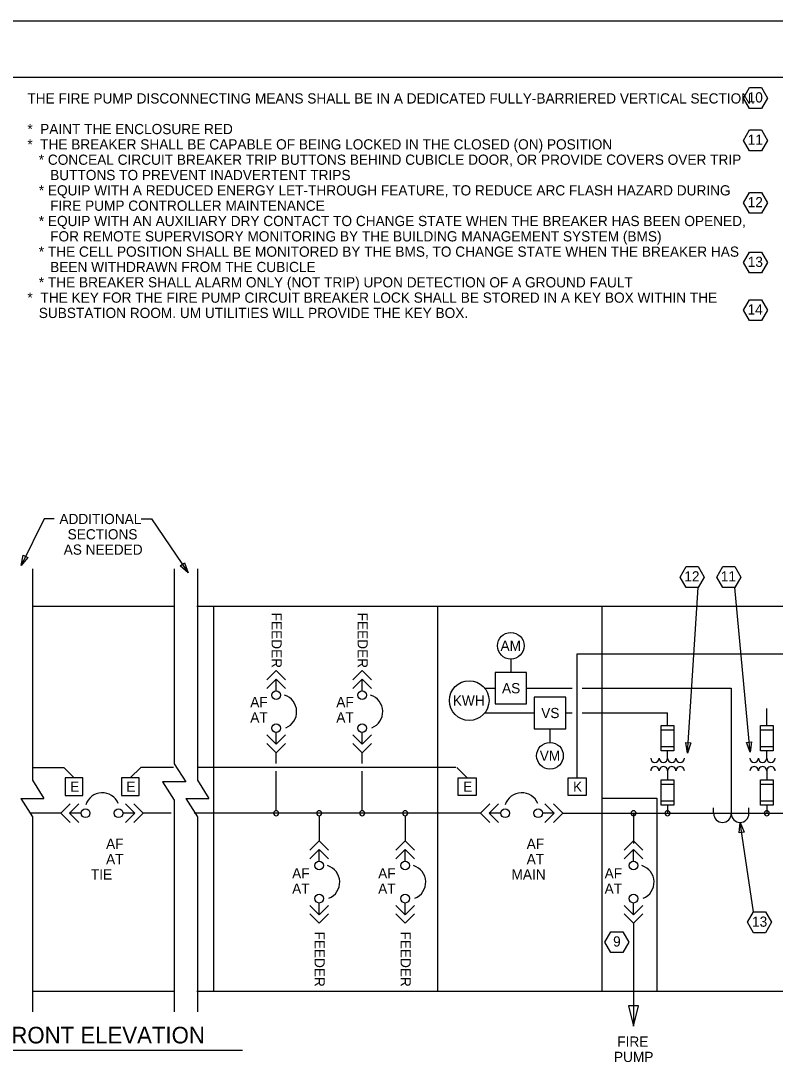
# Model space of a CAD drawing. Extents: x 10251 to 10396, y 10092 to 10197.
# Drawn here: x 10316 to 10365.3, y 10129 to 10196.9 of the extents above; entities that cross this region are included whole.
import ezdxf

# ---------------------------------------------------------------- set-up
doc = ezdxf.new("R2010")
doc.units = 0
for name, color, linetype in [('Default', 7, 'Continuous'), ('G-ANNO-TEXT', 7, 'Continuous'), ('G-ANNO-TTLB', 7, 'Continuous'), ('G-DETL-LINE', 7, 'Continuous'), ('G-DETL-OTLN', 7, 'Continuous'), ('G-DETL-PATT', 7, 'Continuous')]:
    doc.layers.add(name, color=color, linetype=linetype)

msp = doc.modelspace()

# ---------------------------------------------------------------- linework, layer by layer
at = {"layer": 'Default'}
for p, q in [((10323.872, 10164.429), (10324.538, 10164.429)), ((10357.833, 10150.946), (10358.656, 10150.946)), ((10357.833, 10149.298), (10357.833, 10150.946)), ((10357.833, 10150.672), (10358.656, 10150.672)), ((10358.656, 10150.946), (10358.656, 10149.298)), ((10332.687, 10148.464), (10332.687, 10149.17)), ((10338.305, 10148.464), (10338.305, 10149.17)), ((10357.833, 10149.573), (10358.656, 10149.573)), ((10358.656, 10149.298), (10357.833, 10149.298)), ((10338.305, 10145.388), (10338.305, 10147.964)), ((10316.017, 10146.186), (10316.771, 10144.994)), ((10335.496, 10145.063), (10335.496, 10143.418))]:
    msp.add_line(p, q, dxfattribs=at)
for points in [[(10364.774, 10191.899), (10364.382, 10191.219), (10363.598, 10191.219), (10363.206, 10191.899), (10363.598, 10192.578), (10364.382, 10192.578)], [(10355.717, 10136.816), (10355.325, 10136.137), (10354.541, 10136.137), (10354.149, 10136.816), (10354.541, 10137.495), (10355.325, 10137.495)]]:
    msp.add_lwpolyline(points, close=True, dxfattribs=at)
for centre, start, end in [((10332.687, 10145.226), 360, 180), ((10332.687, 10145.226), 180, 0), ((10335.496, 10145.226), 360, 180), ((10335.496, 10145.226), 180, 0), ((10341.114, 10145.226), 360, 180), ((10341.114, 10145.226), 180, 0), ((10364.723, 10145.225), 360, 180), ((10364.723, 10145.225), 180, 0)]:
    msp.add_arc(centre, 0.163, start, end, dxfattribs=at)
at = {"layer": 'G-ANNO-TEXT'}
for p, q in [((10290.736, 10193.271), (10393.489, 10193.271)), ((10317.535, 10164.429), (10316.027, 10161.402)), ((10318.201, 10164.429), (10317.535, 10164.429)), ((10324.538, 10164.429), (10326.937, 10160.917)), ((10316.771, 10161.18), (10316.771, 10147.379)), ((10326.027, 10161.18), (10326.027, 10148.458)), ((10327.542, 10161.18), (10327.542, 10147.379)), ((10359.557, 10149.156), (10360.244, 10159.962)), ((10363.628, 10149.203), (10362.629, 10159.962)), ((10326.027, 10148.458), (10326.781, 10147.266)), ((10316.771, 10147.379), (10317.526, 10146.186)), ((10326.781, 10147.266), (10325.272, 10147.266)), ((10325.272, 10147.266), (10326.027, 10146.073)), ((10327.542, 10147.379), (10328.297, 10146.186)), ((10316.017, 10146.186), (10317.526, 10146.186)), ((10326.027, 10146.073), (10326.027, 10132.272)), ((10326.787, 10146.186), (10328.297, 10146.186)), ((10326.787, 10146.186), (10327.542, 10144.994)), ((10316.771, 10144.994), (10316.771, 10132.272)), ((10327.542, 10144.994), (10327.542, 10132.272)), ((10363.858, 10138.787), (10362.981, 10144.63)), ((10312.797, 10129.772), (10330.484, 10129.772))]:
    msp.add_line(p, q, dxfattribs=at)
for points in [[(10364.774, 10189.137), (10364.382, 10188.458), (10363.598, 10188.458), (10363.206, 10189.137), (10363.598, 10189.816), (10364.382, 10189.816)], [(10364.774, 10185.061), (10364.382, 10184.382), (10363.598, 10184.382), (10363.206, 10185.061), (10363.598, 10185.74), (10364.382, 10185.74)], [(10364.774, 10181.169), (10364.382, 10180.49), (10363.598, 10180.49), (10363.206, 10181.169), (10363.598, 10181.848), (10364.382, 10181.848)], [(10364.774, 10178.059), (10364.382, 10177.38), (10363.598, 10177.38), (10363.206, 10178.059), (10363.598, 10178.738), (10364.382, 10178.738)], [(10316.473, 10161.925), (10316.027, 10161.402), (10316.175, 10162.073)], [(10326.698, 10161.561), (10326.937, 10160.917), (10326.423, 10161.373)], [(10360.636, 10160.641), (10360.244, 10159.962), (10359.46, 10159.962), (10359.068, 10160.641), (10359.46, 10161.32), (10360.244, 10161.32)], [(10363.021, 10160.641), (10362.629, 10159.962), (10361.845, 10159.962), (10361.453, 10160.641), (10361.845, 10161.32), (10362.629, 10161.32)], [(10363.732, 10149.882), (10363.628, 10149.203), (10363.4, 10149.852)], [(10359.765, 10149.811), (10359.557, 10149.156), (10359.433, 10149.832)], [(10362.916, 10143.946), (10362.981, 10144.63), (10363.245, 10143.995)], [(10365.034, 10138.108), (10364.642, 10137.429), (10363.858, 10137.429), (10363.466, 10138.108), (10363.858, 10138.787), (10364.642, 10138.787)]]:
    msp.add_lwpolyline(points, close=True, dxfattribs=at)
at = {"layer": 'G-ANNO-TTLB'}
msp.add_lwpolyline([(10254.096, 10196.937), (10393.006, 10196.937)], dxfattribs=at)
at = {"layer": 'G-DETL-LINE'}
for p, q in [((10348.007, 10155.286), (10348.007, 10154.414)), ((10332.687, 10154.539), (10332.077, 10153.929)), ((10332.687, 10153.985), (10332.077, 10153.374)), ((10332.687, 10154.539), (10333.297, 10153.929)), ((10332.687, 10153.985), (10333.297, 10153.374)), ((10332.687, 10153.221), (10332.687, 10153.985)), ((10338.305, 10154.539), (10337.695, 10153.929)), ((10338.305, 10153.985), (10337.695, 10153.374)), ((10338.305, 10154.539), (10338.915, 10153.929)), ((10338.305, 10153.985), (10338.915, 10153.374)), ((10338.305, 10153.221), (10338.305, 10153.985)), ((10346.305, 10153.386), (10346.98, 10153.386)), ((10349.035, 10153.386), (10352.01, 10153.386)), ((10352.677, 10153.386), (10362.405, 10153.386)), ((10362.405, 10153.386), (10362.405, 10145.225)), ((10364.723, 10150.946), (10364.723, 10152.054)), ((10346.305, 10151.768), (10349.539, 10151.768)), ((10351.594, 10151.768), (10352.01, 10151.768)), ((10352.677, 10151.768), (10358.245, 10151.768)), ((10358.245, 10150.946), (10358.245, 10151.768)), ((10350.567, 10150.74), (10350.567, 10149.849)), ((10364.311, 10150.946), (10365.134, 10150.946)), ((10364.311, 10149.298), (10364.311, 10150.946)), ((10364.311, 10150.672), (10365.134, 10150.672)), ((10365.134, 10150.946), (10365.134, 10149.298)), ((10332.687, 10149.725), (10332.077, 10150.335)), ((10332.687, 10149.725), (10332.687, 10150.488)), ((10332.687, 10149.725), (10333.297, 10150.335)), ((10338.305, 10149.725), (10337.695, 10150.335)), ((10338.305, 10149.725), (10338.305, 10150.488)), ((10338.305, 10149.725), (10338.915, 10150.335)), ((10332.687, 10149.17), (10332.077, 10149.78)), ((10332.687, 10149.17), (10333.297, 10149.78)), ((10338.305, 10149.17), (10337.695, 10149.78)), ((10338.305, 10149.17), (10338.915, 10149.78)), ((10358.245, 10148.817), (10358.245, 10149.298)), ((10364.311, 10149.573), (10365.134, 10149.573)), ((10365.134, 10149.298), (10364.311, 10149.298)), ((10364.723, 10148.817), (10364.723, 10149.298)), ((10332.687, 10145.388), (10332.687, 10147.964)), ((10358.245, 10147.993), (10358.245, 10147.404)), ((10364.723, 10147.993), (10364.723, 10147.404)), ((10357.833, 10147.404), (10358.656, 10147.404)), ((10357.833, 10145.756), (10357.833, 10147.404)), ((10357.833, 10147.129), (10358.656, 10147.129)), ((10358.656, 10147.404), (10358.656, 10145.756)), ((10364.311, 10147.404), (10365.134, 10147.404)), ((10364.311, 10145.756), (10364.311, 10147.404)), ((10364.311, 10147.129), (10365.134, 10147.129)), ((10365.134, 10147.404), (10365.134, 10145.756)), ((10318.636, 10145.225), (10319.246, 10145.836)), ((10319.19, 10145.225), (10319.801, 10145.836)), ((10323.45, 10145.225), (10322.84, 10145.836)), ((10324.005, 10145.225), (10323.395, 10145.836)), ((10346.032, 10145.225), (10346.642, 10145.836)), ((10346.586, 10145.225), (10347.197, 10145.836)), ((10350.846, 10145.225), (10350.236, 10145.836)), ((10351.401, 10145.225), (10350.791, 10145.836)), ((10357.833, 10146.03), (10358.656, 10146.03)), ((10364.311, 10146.03), (10365.134, 10146.03)), ((10318.636, 10145.225), (10316.607, 10145.225)), ((10318.636, 10145.225), (10319.246, 10144.616)), ((10319.19, 10145.225), (10319.801, 10144.616)), ((10319.954, 10145.225), (10319.19, 10145.225)), ((10323.45, 10145.225), (10322.687, 10145.225)), ((10323.45, 10145.225), (10322.84, 10144.616)), ((10324.005, 10145.225), (10323.395, 10144.616)), ((10325.829, 10145.225), (10324.005, 10145.225)), ((10346.032, 10145.225), (10327.331, 10145.225)), ((10346.032, 10145.225), (10346.642, 10144.616)), ((10346.586, 10145.225), (10347.197, 10144.616)), ((10347.35, 10145.225), (10346.586, 10145.225)), ((10350.846, 10145.225), (10350.083, 10145.225)), ((10350.846, 10145.225), (10350.236, 10144.616)), ((10351.401, 10145.225), (10350.791, 10144.616)), ((10351.401, 10145.225), (10369.648, 10145.225)), ((10356.023, 10145.225), (10356.023, 10143.255)), ((10358.656, 10145.756), (10357.833, 10145.756)), ((10358.245, 10145.756), (10358.245, 10145.225)), ((10361.255, 10145.204), (10361.255, 10145.576)), ((10363.556, 10145.204), (10363.556, 10145.576)), ((10365.134, 10145.756), (10364.311, 10145.756)), ((10364.723, 10145.756), (10364.723, 10145.225)), ((10341.114, 10145.063), (10341.114, 10143.418)), ((10335.496, 10143.418), (10334.886, 10142.808)), ((10335.496, 10143.418), (10336.106, 10142.808)), ((10341.114, 10143.418), (10340.504, 10142.808)), ((10341.114, 10143.418), (10341.724, 10142.808)), ((10356.023, 10143.418), (10355.413, 10142.808)), ((10356.023, 10143.418), (10356.633, 10142.808)), ((10335.496, 10142.864), (10334.886, 10142.253)), ((10335.496, 10142.864), (10336.106, 10142.253)), ((10335.496, 10142.1), (10335.496, 10142.864)), ((10341.114, 10142.864), (10340.504, 10142.253)), ((10341.114, 10142.864), (10341.724, 10142.253)), ((10341.114, 10142.1), (10341.114, 10142.864)), ((10356.023, 10142.864), (10355.413, 10142.253)), ((10356.023, 10142.864), (10356.633, 10142.253)), ((10356.023, 10142.1), (10356.023, 10142.864)), ((10335.496, 10138.604), (10334.886, 10139.214)), ((10335.496, 10138.604), (10335.496, 10139.367)), ((10335.496, 10138.604), (10336.106, 10139.214)), ((10341.114, 10138.604), (10340.504, 10139.214)), ((10341.114, 10138.604), (10341.114, 10139.367)), ((10341.114, 10138.604), (10341.724, 10139.214)), ((10356.023, 10138.604), (10355.413, 10139.214)), ((10356.023, 10138.604), (10356.023, 10139.367)), ((10356.023, 10138.604), (10356.633, 10139.214)), ((10335.496, 10138.049), (10334.886, 10138.659)), ((10335.496, 10138.049), (10336.106, 10138.659)), ((10341.114, 10138.049), (10340.504, 10138.659)), ((10341.114, 10138.049), (10341.724, 10138.659)), ((10356.023, 10138.049), (10355.413, 10138.659)), ((10356.023, 10138.049), (10356.633, 10138.659)), ((10356.023, 10138.049), (10356.023, 10131.334))]:
    msp.add_line(p, q, dxfattribs=at)
msp.add_lwpolyline([(10355.689, 10132.668), (10356.023, 10131.334), (10356.356, 10132.668)], close=True, dxfattribs=at)
for centre in [(10332.687, 10152.933), (10338.305, 10152.933), (10332.687, 10150.776), (10338.305, 10150.776), (10320.242, 10145.225), (10322.4, 10145.225), (10347.637, 10145.225), (10349.795, 10145.225), (10335.496, 10141.812), (10341.114, 10141.812), (10356.023, 10141.812), (10335.496, 10139.655), (10341.114, 10139.655), (10356.023, 10139.655)]:
    msp.add_circle(centre, 0.287, dxfattribs=at)
for centre, radius, start, end in [((10332.897, 10151.848), 1.13, 291.91165, 72.57617), ((10338.515, 10151.848), 1.13, 291.91165, 72.57617), ((10357.42, 10148.817), 0.275, 180.00003, 0.00003), ((10357.97, 10148.817), 0.275, 180.00003, 0.00003), ((10358.519, 10148.817), 0.275, 180.00003, 0.00003), ((10359.069, 10148.817), 0.275, 180.00003, 0.00003), ((10363.898, 10148.817), 0.275, 180.00003, 0.00003), ((10364.448, 10148.817), 0.275, 180.00003, 0.00003), ((10364.997, 10148.817), 0.275, 180.00003, 0.00003), ((10357.42, 10147.993), 0.275, 0.00003, 180.00003), ((10357.97, 10147.993), 0.275, 0.00003, 180.00003), ((10358.519, 10147.993), 0.275, 0.00003, 180.00003), ((10359.069, 10147.993), 0.275, 0.00003, 180.00003), ((10363.898, 10147.993), 0.275, 0.00003, 180.00003), ((10364.448, 10147.993), 0.275, 0.00003, 180.00003), ((10364.997, 10147.993), 0.275, 0.00003, 180.00003), ((10321.328, 10145.436), 1.13, 21.91165, 162.57617), ((10348.723, 10145.436), 1.13, 21.91165, 162.57617), ((10338.305, 10145.226), 0.163, 360, 180), ((10338.305, 10145.226), 0.163, 360, 180), ((10338.305, 10145.226), 0.163, 180, 0), ((10338.305, 10145.226), 0.163, 180, 0), ((10356.023, 10145.226), 0.163, 360, 180), ((10356.023, 10145.226), 0.163, 180, 0), ((10358.245, 10145.225), 0.163, 360, 180), ((10358.245, 10145.225), 0.163, 180, 0), ((10361.831, 10145.205), 0.575, 180, 0), ((10362.981, 10145.205), 0.575, 180, 0), ((10335.706, 10140.727), 1.13, 291.91165, 72.57617), ((10341.324, 10140.727), 1.13, 291.91165, 72.57617), ((10356.233, 10140.727), 1.13, 291.91165, 72.57617)]:
    msp.add_arc(centre, radius, start, end, dxfattribs=at)
at = {"layer": 'G-DETL-OTLN'}
for p, q in [((10325.994, 10158.727), (10316.771, 10158.727)), ((10392.803, 10158.727), (10327.51, 10158.727)), ((10328.585, 10158.727), (10328.585, 10133.6)), ((10343.212, 10158.727), (10343.212, 10133.6)), ((10353.945, 10158.727), (10353.945, 10133.6)), ((10325.994, 10133.6), (10316.771, 10133.6)), ((10392.803, 10133.6), (10327.51, 10133.6))]:
    msp.add_line(p, q, dxfattribs=at)
msp.add_lwpolyline([(10353.945, 10146.205), (10357.539, 10146.205), (10357.539, 10133.6)], dxfattribs=at)
at = {"layer": 'G-DETL-PATT'}
for p, q in [((10316.797, 10148.214), (10318.815, 10148.214)), ((10319.494, 10147.535), (10318.815, 10148.214)), ((10323.163, 10147.535), (10323.842, 10148.214)), ((10325.976, 10148.214), (10323.842, 10148.214)), ((10344.427, 10148.214), (10327.521, 10148.214)), ((10345.159, 10147.535), (10344.48, 10148.214))]:
    msp.add_line(p, q, dxfattribs=at)
msp.add_lwpolyline([(10352.344, 10147.535), (10352.344, 10155.619), (10377.931, 10155.619)], dxfattribs=at)
for points in [[(10349.035, 10154.414), (10346.98, 10154.414), (10346.98, 10152.359), (10349.035, 10152.359)], [(10351.594, 10152.795), (10349.539, 10152.795), (10349.539, 10150.74), (10351.594, 10150.74)], [(10320.073, 10146.377), (10320.073, 10147.535), (10318.916, 10147.535), (10318.916, 10146.377)], [(10323.742, 10146.377), (10323.742, 10147.535), (10322.584, 10147.535), (10322.584, 10146.377)], [(10344.58, 10146.377), (10344.58, 10147.535), (10345.738, 10147.535), (10345.738, 10146.377)], [(10351.765, 10146.377), (10351.765, 10147.535), (10352.922, 10147.535), (10352.922, 10146.377)]]:
    msp.add_lwpolyline(points, close=True, dxfattribs=at)
for centre, radius in [((10348.007, 10156.156), 0.87), ((10345.295, 10152.577), 1.294), ((10350.567, 10148.979), 0.87)]:
    msp.add_circle(centre, radius, dxfattribs=at)

# ---------------------------------------------------------------- texts
at = {"layer": 'Default'}
for s, height, p in [('10', 0.6667, (10363.475, 10191.609)), ('9', 0.667, (10354.689, 10136.526))]:
    msp.add_text(s, height=height, dxfattribs=at).set_placement(p)
at = {"layer": 'G-ANNO-TEXT'}
for s, height, p in [('THE FIRE PUMP DISCONNECTING MEANS SHALL BE IN A DEDICATED FULLY-BARRIERED VERTICAL SECTION.', 0.66667, (10316.444, 10191.541)), ('*', 0.667, (10316.444, 10189.541)), (' PAINT THE ENCLOSURE RED', 0.66667, (10317.028, 10189.541)), ('11', 0.6667, (10363.475, 10188.847)), ('*', 0.667, (10316.444, 10188.541)), (' THE BREAKER SHALL BE CAPABLE OF BEING LOCKED IN THE CLOSED (ON) POSITION', 0.66667, (10317.028, 10188.541)), ('   * CONCEAL CIRCUIT BREAKER TRIP BUTTONS BEHIND CUBICLE DOOR, OR PROVIDE COVERS OVER TRIP', 0.66667, (10316.444, 10187.541)), ('      BUTTONS TO PREVENT INADVERTENT TRIPS', 0.66667, (10316.444, 10186.541)), ('   * EQUIP WITH A REDUCED ENERGY LET-THROUGH FEATURE, TO REDUCE ARC FLASH HAZARD DURING', 0.66667, (10316.444, 10185.541)), ('      FIRE PUMP CONTROLLER MAINTENANCE', 0.66667, (10316.444, 10184.541)), ('12', 0.6667, (10363.475, 10184.771)), ('   * EQUIP WITH AN AUXILIARY DRY CONTACT TO CHANGE STATE WHEN THE BREAKER HAS BEEN OPENED,', 0.66667, (10316.444, 10183.541)), ('      FOR REMOTE SUPERVISORY MONITORING BY THE BUILDING MANAGEMENT SYSTEM (BMS)', 0.66667, (10316.444, 10182.541)), ('   * THE CELL POSITION SHALL BE MONITORED BY THE BMS, TO CHANGE STATE WHEN THE BREAKER HAS', 0.66667, (10316.444, 10181.541)), ('      BEEN WITHDRAWN FROM THE CUBICLE', 0.66667, (10316.444, 10180.541)), ('13', 0.6667, (10363.481, 10180.879)), ('   * THE BREAKER SHALL ALARM ONLY (NOT TRIP) UPON DETECTION OF A GROUND FAULT', 0.66667, (10316.444, 10179.541)), ('* ', 0.6667, (10316.444, 10178.541)), ('THE KEY FOR THE FIRE PUMP CIRCUIT BREAKER LOCK SHALL BE STORED IN A KEY BOX WITHIN THE', 0.66667, (10317.297, 10178.541)), ('14', 0.6667, (10363.467, 10177.769)), ('   SUBSTATION ROOM. UM UTILITIES WILL PROVIDE THE KEY BOX.', 0.66667, (10316.444, 10177.541)), ('ADDITIONAL', 0.6667, (10318.534, 10164.096)), ('SECTIONS', 0.6667, (10319.072, 10163.096)), ('AS NEEDED', 0.6667, (10318.814, 10162.096)), ('12', 0.6667, (10359.338, 10160.351)), ('11', 0.6667, (10361.722, 10160.351)), ('AM', 0.6667, (10347.337, 10155.823)), ('AS', 0.6667, (10347.436, 10153.053)), ('   AF', 0.6667, (10330.253, 10152.145)), ('   AF', 0.6667, (10335.871, 10152.145)), ('KWH', 0.6667, (10344.22, 10152.244)), ('VS', 0.6667, (10349.996, 10151.434)), ('   AT', 0.6667, (10330.253, 10151.145)), ('   AT', 0.6667, (10335.871, 10151.145)), ('VM', 0.6667, (10349.898, 10148.646)), ('    AF', 0.6667, (10320.591, 10142.898)), ('    AF', 0.6667, (10348.055, 10142.898)), ('    AT', 0.6667, (10320.591, 10141.898)), ('    AT', 0.6667, (10348.055, 10141.898)), ('TIE', 0.6667, (10320.591, 10140.898)), ('   AF', 0.6667, (10332.988, 10140.972)), ('   AF', 0.6667, (10338.606, 10140.972)), ('MAIN', 0.6667, (10348.055, 10140.898)), ('   AF', 0.6667, (10353.391, 10140.972)), ('   AT', 0.6667, (10332.988, 10139.972)), ('   AT', 0.6667, (10338.606, 10139.972)), ('   AT', 0.6667, (10353.391, 10139.972)), ('13', 0.6667, (10363.761, 10137.818)), ('FRONT ELEVATION', 1.08333, (10314.511, 10130.205)), ('FIRE', 0.6667, (10354.961, 10129.991)), ('PUMP', 0.6667, (10354.746, 10128.991))]:
    msp.add_text(s, height=height, dxfattribs=at).set_placement(p)
for p in [(10332.384, 10158.317), (10338.002, 10158.317), (10335.192, 10137.512), (10340.809, 10137.512)]:
    msp.add_text('FEEDER', height=0.6667, rotation=270, dxfattribs=at).set_placement(p)
at = {"layer": 'G-DETL-PATT'}
for s, p in [('E', (10319.237, 10146.623)), ('E', (10322.906, 10146.623)), ('E', (10344.902, 10146.623)), ('K', (10352.074, 10146.623))]:
    msp.add_text(s, height=0.667, rotation=360, dxfattribs=at).set_placement(p)

doc.saveas('drawing.dxf')
